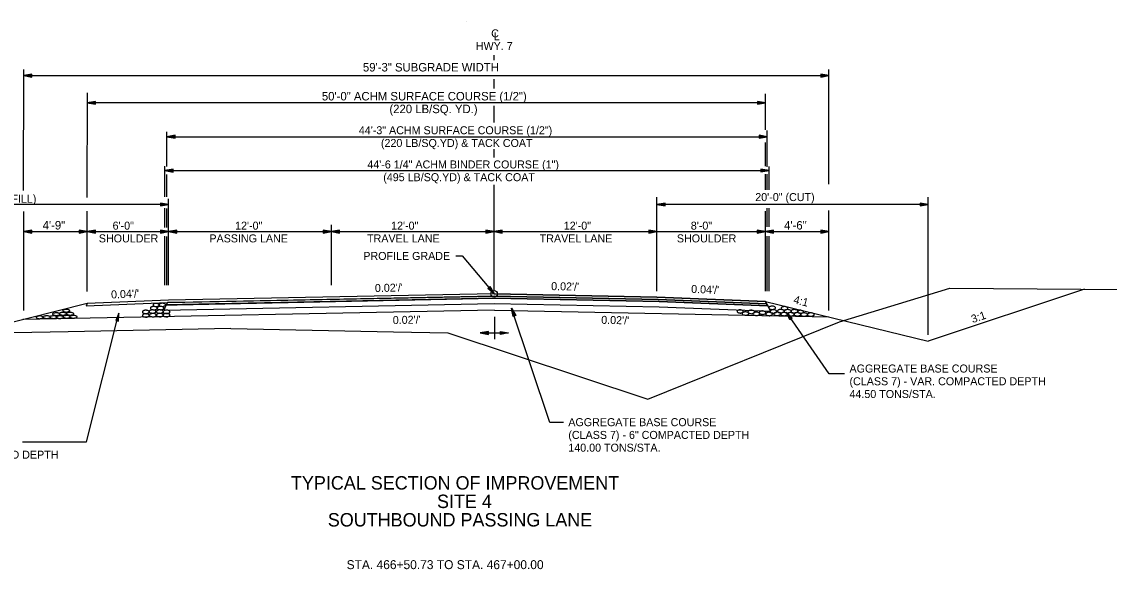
# Model space of a CAD drawing. Extents: x 1398183 to 1398373, y 1967240 to 1968889.
# Drawn here: x 1398225.6 to 1398305.8, y 1967766.3 to 1967806.6 of the extents above; entities that cross this region are included whole.
import ezdxf

# ---------------------------------------------------------------- set-up
doc = ezdxf.new("R2010")
doc.units = 0
for name, color, linetype in [('1', 7, 'Continuous'), ('10', 7, 'Continuous'), ('19', 7, 'Continuous'), ('42', 7, 'Continuous'), ('7', 7, 'Continuous'), ('Level 1', 7, 'Continuous'), ('Level 9', 7, 'Continuous')]:
    doc.layers.add(name, color=color, linetype=linetype)

# ---------------------------------------------------------------- blocks, each defined once
blk = doc.blocks.new('ROCKS')
at = {"layer": '1'}
blk.add_spline([(0.013, 0.06), (0.053, 0.053), (0.107, 0.033), (0.133, 0.013), (0.133, -0.007), (0.12, -0.033), (0.107, -0.04), (0.073, -0.053), (0.033, -0.067), (0.013, -0.067), (-0.02, -0.06), (-0.06, -0.053), (-0.087, -0.047), (-0.113, -0.02), (-0.113, -0.007), (-0.107, 0.02), (-0.087, 0.033), (-0.067, 0.047), (-0.033, 0.053), (-0.02, 0.06), (0.013, 0.06)], degree=3, dxfattribs=at)
blk = doc.blocks.new('4TO1 ABC')
at = {"layer": '1', "xscale": 0.1312491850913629, "yscale": 0.1312491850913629, "rotation": 180}
for p in [(0.00175, -0.00875), (-0.03325, -0.0385), (-0.016625, -0.023625), (0, -0.0385), (0.018375, -0.023625), (0.034125, -0.04025), (0.051625, -0.025375), (0.06475, -0.04025), (0.098, -0.04025), (0.133, -0.041125)]:
    blk.add_blockref('ROCKS', p, dxfattribs=at)

msp = doc.modelspace()

# ---------------------------------------------------------------- linework, layer by layer
at = {"layer": '1'}
msp.add_line((1398258.385, 1967806.631), (1398258.385, 1967806.631), dxfattribs=at)
msp.add_line((1398258.385, 1967806.631), (1398258.385, 1967806.631), dxfattribs=at)
at = {"layer": '19'}
for p, q in [((1398225.76, 1967794.194), (1398225.776, 1967803.114)), ((1398226.376, 1967802.762), (1398225.776, 1967802.657)), ((1398225.776, 1967802.657), (1398285.131, 1967802.657)), ((1398225.776, 1967802.657), (1398226.376, 1967802.552)), ((1398226.376, 1967802.707), (1398225.936, 1967802.672)), ((1398225.936, 1967802.642), (1398226.376, 1967802.602)), ((1398226.376, 1967802.552), (1398226.376, 1967802.762)), ((1398284.531, 1967802.762), (1398284.531, 1967802.552)), ((1398285.131, 1967802.657), (1398284.531, 1967802.762)), ((1398284.971, 1967802.672), (1398284.531, 1967802.707)), ((1398284.531, 1967802.552), (1398285.131, 1967802.657)), ((1398284.531, 1967802.602), (1398284.971, 1967802.642)), ((1398285.125, 1967794.648), (1398285.131, 1967803.114)), ((1398230.434, 1967793.677), (1398230.459, 1967801.394)), ((1398280.45, 1967798.665), (1398280.452, 1967801.304)), ((1398231.052, 1967800.762), (1398230.452, 1967800.657)), ((1398230.452, 1967800.657), (1398231.052, 1967800.552)), ((1398280.452, 1967800.657), (1398230.452, 1967800.657)), ((1398231.052, 1967800.707), (1398230.612, 1967800.672)), ((1398230.612, 1967800.642), (1398231.052, 1967800.602)), ((1398231.052, 1967800.552), (1398231.052, 1967800.762)), ((1398279.852, 1967800.762), (1398279.852, 1967800.552)), ((1398280.452, 1967800.657), (1398279.852, 1967800.762)), ((1398280.292, 1967800.672), (1398279.852, 1967800.707)), ((1398279.852, 1967800.552), (1398280.452, 1967800.657)), ((1398279.852, 1967800.602), (1398280.292, 1967800.642)), ((1398280.575, 1967795.932), (1398280.575, 1967798.613)), ((1398236.32, 1967795.966), (1398236.32, 1967798.516)), ((1398236.92, 1967798.262), (1398236.32, 1967798.157)), ((1398236.32, 1967798.157), (1398280.575, 1967798.157)), ((1398236.32, 1967798.157), (1398236.92, 1967798.052)), ((1398236.92, 1967798.207), (1398236.48, 1967798.172)), ((1398236.48, 1967798.142), (1398236.92, 1967798.102)), ((1398236.92, 1967798.052), (1398236.92, 1967798.262)), ((1398279.975, 1967798.263), (1398279.975, 1967798.053)), ((1398280.575, 1967798.158), (1398279.975, 1967798.263)), ((1398280.415, 1967798.173), (1398279.975, 1967798.208)), ((1398279.975, 1967798.053), (1398280.575, 1967798.158)), ((1398279.975, 1967798.103), (1398280.415, 1967798.143)), ((1398280.447, 1967795.971), (1398280.449, 1967797.722)), ((1398236.181, 1967793.713), (1398236.181, 1967795.982)), ((1398236.781, 1967795.762), (1398236.181, 1967795.657)), ((1398236.181, 1967795.657), (1398280.711, 1967795.657)), ((1398236.181, 1967795.657), (1398236.781, 1967795.552)), ((1398236.781, 1967795.707), (1398236.341, 1967795.672)), ((1398236.341, 1967795.642), (1398236.781, 1967795.602)), ((1398236.781, 1967795.552), (1398236.781, 1967795.762)), ((1398280.111, 1967795.763), (1398280.111, 1967795.553)), ((1398280.711, 1967795.658), (1398280.111, 1967795.763)), ((1398280.551, 1967795.673), (1398280.111, 1967795.708)), ((1398280.111, 1967795.553), (1398280.711, 1967795.658)), ((1398280.111, 1967795.603), (1398280.551, 1967795.643)), ((1398280.711, 1967794.242), (1398280.711, 1967795.962)), ((1398236.32, 1967793.714), (1398236.32, 1967795.359)), ((1398280.445, 1967794.242), (1398280.446, 1967795.387)), ((1398280.575, 1967794.242), (1398280.575, 1967795.387)), ((1398236.447, 1967793.157), (1398212.447, 1967793.157)), ((1398235.847, 1967793.262), (1398235.847, 1967793.052)), ((1398236.447, 1967793.157), (1398235.847, 1967793.262)), ((1398236.287, 1967793.172), (1398235.847, 1967793.207)), ((1398235.847, 1967793.052), (1398236.447, 1967793.157)), ((1398235.847, 1967793.102), (1398236.287, 1967793.142)), ((1398272.447, 1967786.756), (1398272.447, 1967793.703)), ((1398273.047, 1967793.262), (1398272.447, 1967793.157)), ((1398292.447, 1967793.157), (1398272.447, 1967793.157)), ((1398272.447, 1967793.157), (1398273.047, 1967793.052)), ((1398273.047, 1967793.207), (1398272.607, 1967793.172)), ((1398272.607, 1967793.142), (1398273.047, 1967793.102)), ((1398273.047, 1967793.052), (1398273.047, 1967793.262)), ((1398291.847, 1967793.262), (1398291.847, 1967793.052)), ((1398292.447, 1967793.157), (1398291.847, 1967793.262)), ((1398292.287, 1967793.172), (1398291.847, 1967793.207)), ((1398291.847, 1967793.052), (1398292.447, 1967793.157)), ((1398291.847, 1967793.102), (1398292.287, 1967793.142)), ((1398225.769, 1967785.335), (1398225.769, 1967792.646)), ((1398230.447, 1967786.754), (1398230.447, 1967792.672)), ((1398236.182, 1967791.464), (1398236.182, 1967792.88)), ((1398236.32, 1967791.467), (1398236.32, 1967792.874)), ((1398280.447, 1967786.757), (1398280.447, 1967792.655)), ((1398280.575, 1967791.516), (1398280.575, 1967792.885)), ((1398280.711, 1967791.514), (1398280.711, 1967792.881)), ((1398285.125, 1967785.35), (1398285.124, 1967792.711)), ((1398248.447, 1967787.2), (1398248.447, 1967791.661)), ((1398226.369, 1967791.262), (1398225.769, 1967791.157)), ((1398225.769, 1967791.157), (1398230.447, 1967791.157)), ((1398225.769, 1967791.157), (1398226.369, 1967791.052)), ((1398226.369, 1967791.207), (1398225.929, 1967791.172)), ((1398225.929, 1967791.142), (1398226.369, 1967791.102)), ((1398226.369, 1967791.052), (1398226.369, 1967791.262)), ((1398229.847, 1967791.262), (1398229.847, 1967791.052)), ((1398230.447, 1967791.157), (1398229.847, 1967791.262)), ((1398230.287, 1967791.172), (1398229.847, 1967791.207)), ((1398229.847, 1967791.052), (1398230.447, 1967791.157)), ((1398229.847, 1967791.102), (1398230.287, 1967791.142)), ((1398231.047, 1967791.262), (1398230.447, 1967791.157)), ((1398230.447, 1967791.157), (1398246.447, 1967791.157)), ((1398230.447, 1967791.157), (1398231.047, 1967791.052)), ((1398231.047, 1967791.207), (1398230.607, 1967791.172)), ((1398230.607, 1967791.142), (1398231.047, 1967791.102)), ((1398231.047, 1967791.052), (1398231.047, 1967791.262)), ((1398235.847, 1967791.262), (1398235.847, 1967791.052)), ((1398236.447, 1967791.157), (1398235.847, 1967791.262)), ((1398236.287, 1967791.172), (1398235.847, 1967791.207)), ((1398235.847, 1967791.052), (1398236.447, 1967791.157)), ((1398235.847, 1967791.102), (1398236.287, 1967791.142)), ((1398236.182, 1967787.199), (1398236.182, 1967790.812)), ((1398236.32, 1967787.199), (1398236.32, 1967790.809)), ((1398237.047, 1967791.262), (1398236.447, 1967791.157)), ((1398236.447, 1967791.157), (1398237.047, 1967791.052)), ((1398237.047, 1967791.207), (1398236.607, 1967791.172)), ((1398236.607, 1967791.142), (1398237.047, 1967791.102)), ((1398237.047, 1967791.052), (1398237.047, 1967791.262)), ((1398246.447, 1967791.157), (1398258.447, 1967791.157)), ((1398247.847, 1967791.262), (1398247.847, 1967791.052)), ((1398248.447, 1967791.157), (1398247.847, 1967791.262)), ((1398248.287, 1967791.172), (1398247.847, 1967791.207)), ((1398247.847, 1967791.052), (1398248.447, 1967791.157)), ((1398247.847, 1967791.102), (1398248.287, 1967791.142)), ((1398249.047, 1967791.262), (1398248.447, 1967791.157)), ((1398248.447, 1967791.157), (1398249.047, 1967791.052)), ((1398249.047, 1967791.207), (1398248.607, 1967791.172)), ((1398248.607, 1967791.142), (1398249.047, 1967791.102)), ((1398249.047, 1967791.052), (1398249.047, 1967791.262)), ((1398258.447, 1967791.157), (1398280.447, 1967791.157)), ((1398259.847, 1967791.262), (1398259.847, 1967791.052)), ((1398260.447, 1967791.157), (1398259.847, 1967791.262)), ((1398260.287, 1967791.172), (1398259.847, 1967791.207)), ((1398259.847, 1967791.052), (1398260.447, 1967791.157)), ((1398259.847, 1967791.102), (1398260.287, 1967791.142)), ((1398261.047, 1967791.262), (1398260.447, 1967791.157)), ((1398260.447, 1967791.157), (1398261.047, 1967791.052)), ((1398261.047, 1967791.207), (1398260.607, 1967791.172)), ((1398260.607, 1967791.142), (1398261.047, 1967791.102)), ((1398261.047, 1967791.052), (1398261.047, 1967791.262)), ((1398271.847, 1967791.262), (1398271.847, 1967791.052)), ((1398272.447, 1967791.157), (1398271.847, 1967791.262)), ((1398272.287, 1967791.172), (1398271.847, 1967791.207)), ((1398271.847, 1967791.052), (1398272.447, 1967791.157)), ((1398271.847, 1967791.102), (1398272.287, 1967791.142)), ((1398279.847, 1967791.262), (1398279.847, 1967791.052)), ((1398280.447, 1967791.157), (1398279.847, 1967791.262)), ((1398280.287, 1967791.172), (1398279.847, 1967791.207)), ((1398279.847, 1967791.052), (1398280.447, 1967791.157)), ((1398279.847, 1967791.102), (1398280.287, 1967791.142)), ((1398281.047, 1967791.262), (1398280.447, 1967791.158)), ((1398281.047, 1967791.262), (1398280.447, 1967791.157)), ((1398280.447, 1967791.158), (1398281.047, 1967791.052)), ((1398280.447, 1967791.157), (1398285.124, 1967791.157)), ((1398280.447, 1967791.157), (1398281.047, 1967791.052)), ((1398280.576, 1967786.757), (1398280.576, 1967790.819)), ((1398281.047, 1967791.207), (1398280.607, 1967791.173)), ((1398281.047, 1967791.207), (1398280.607, 1967791.172)), ((1398280.607, 1967791.143), (1398281.047, 1967791.102)), ((1398280.607, 1967791.142), (1398281.047, 1967791.102)), ((1398280.711, 1967786.757), (1398280.711, 1967790.821)), ((1398281.047, 1967791.052), (1398281.047, 1967791.262)), ((1398281.047, 1967791.052), (1398281.047, 1967791.262)), ((1398284.524, 1967791.262), (1398284.524, 1967791.052)), ((1398285.124, 1967791.157), (1398284.524, 1967791.262)), ((1398284.964, 1967791.172), (1398284.524, 1967791.207)), ((1398284.524, 1967791.052), (1398285.124, 1967791.157)), ((1398284.524, 1967791.102), (1398284.964, 1967791.142)), ((1398259.981, 1967786.965), (1398260.141, 1967787.099)), ((1398260.447, 1967786.573), (1398259.981, 1967786.965)), ((1398260.337, 1967786.688), (1398260.025, 1967786.996)), ((1398260.108, 1967787.067), (1398260.355, 1967786.706)), ((1398260.141, 1967787.099), (1398260.447, 1967786.573)), ((1398303.957, 1967786.909), (1398292.448, 1967783.072)), ((1398230.447, 1967785.854), (1398212.447, 1967781.354)), ((1398230.447, 1967785.854), (1398230.362, 1967785.684)), ((1398236.447, 1967786.094), (1398230.447, 1967785.854)), ((1398236.362, 1967785.924), (1398236.277, 1967785.754)), ((1398260.447, 1967786.574), (1398236.447, 1967786.094)), ((1398260.447, 1967786.574), (1398272.447, 1967786.334)), ((1398271.924, 1967786.004), (1398260.447, 1967786.24)), ((1398272.447, 1967786.334), (1398280.447, 1967786.014)), ((1398280.447, 1967786.014), (1398292.448, 1967783.072)), ((1398280.447, 1967786.014), (1398280.532, 1967785.844)), ((1398280.532, 1967785.844), (1398280.617, 1967785.674)), ((1398260.47, 1967785.362), (1398225.697, 1967784.666)), ((1398230.397, 1967775.667), (1398232.788, 1967785.143)), ((1398232.79, 1967785.151), (1398232.546, 1967784.593)), ((1398232.741, 1967785), (1398232.599, 1967784.584)), ((1398232.701, 1967784.557), (1398232.768, 1967784.993)), ((1398232.749, 1967784.545), (1398232.79, 1967785.151)), ((1398236.277, 1967785.754), (1398236.088, 1967785.375)), ((1398260.47, 1967785.362), (1398285.119, 1967784.869)), ((1398264.544, 1967777.089), (1398261.739, 1967785.509)), ((1398261.841, 1967784.91), (1398261.739, 1967785.509)), ((1398261.739, 1967785.509), (1398262.038, 1967784.978)), ((1398261.887, 1967784.927), (1398261.777, 1967785.354)), ((1398261.804, 1967785.364), (1398261.987, 1967784.964)), ((1398262.038, 1967784.978), (1398261.841, 1967784.91)), ((1398272.612, 1967785.619), (1398280.809, 1967785.291)), ((1398280.617, 1967785.674), (1398280.809, 1967785.291)), ((1398280.809, 1967785.291), (1398280.617, 1967785.674)), ((1398285.136, 1967780.661), (1398281.991, 1967785.213)), ((1398282.244, 1967784.661), (1398281.991, 1967785.213)), ((1398281.991, 1967785.213), (1398282.416, 1967784.778)), ((1398282.284, 1967784.689), (1398282.067, 1967785.073)), ((1398282.091, 1967785.089), (1398282.371, 1967784.75)), ((1398232.546, 1967784.593), (1398232.749, 1967784.545)), ((1398282.416, 1967784.778), (1398282.244, 1967784.661)), ((1398286.287, 1967780.661), (1398285.136, 1967780.661)), ((1398265.557, 1967777.089), (1398264.544, 1967777.089)), ((1398225.669, 1967775.667), (1398230.397, 1967775.667))]:
    msp.add_line(p, q, dxfattribs=at)
for points in [[(1398257.611, 1967789.36), (1398258.101, 1967789.36), (1398260.447, 1967786.573)], [(1398257.039, 1967783.694), (1398271.783, 1967778.793), (1398285.898, 1967784.503), (1398294.031, 1967786.983), (1398323.027, 1967786.767)], [(1398230.362, 1967785.684), (1398236.362, 1967785.924), (1398260.447, 1967786.406), (1398272.532, 1967786.164), (1398280.532, 1967785.844)], [(1398260.447, 1967786.24), (1398236.277, 1967785.754), (1398236.088, 1967785.375)], [(1398236.088, 1967785.375), (1398260.447, 1967785.865), (1398272.612, 1967785.619)], [(1398236.088, 1967785.375), (1398260.447, 1967785.865), (1398272.612, 1967785.619)], [(1398272.616, 1967785.994), (1398260.447, 1967786.24), (1398236.277, 1967785.754)], [(1398280.617, 1967785.674), (1398272.616, 1967785.994), (1398271.924, 1967786.004)], [(1398272.616, 1967785.994), (1398280.617, 1967785.674)], [(1398272.612, 1967785.619), (1398280.809, 1967785.291)], [(1398229.04, 1967783.774), (1398225.041, 1967783.694)], [(1398241.04, 1967784.014), (1398229.04, 1967783.774)], [(1398241.04, 1967784.014), (1398253.04, 1967783.774)], [(1398253.04, 1967783.774), (1398257.039, 1967783.694)]]:
    msp.add_lwpolyline(points, dxfattribs=at)
for points in [[(1398230.362, 1967785.684), (1398236.362, 1967785.924), (1398260.447, 1967786.406), (1398272.532, 1967786.164), (1398280.532, 1967785.844), (1398280.447, 1967786.014), (1398272.447, 1967786.334), (1398260.447, 1967786.574), (1398236.447, 1967786.094), (1398230.447, 1967785.854)], [(1398236.362, 1967785.924), (1398236.277, 1967785.754), (1398237.078, 1967785.77), (1398260.447, 1967786.24), (1398272.616, 1967785.994), (1398280.617, 1967785.674), (1398280.532, 1967785.844), (1398272.532, 1967786.164), (1398260.447, 1967786.406), (1398237.02, 1967785.937)]]:
    msp.add_lwpolyline(points, close=True, dxfattribs=at)
at = {"layer": '42'}
for p, q in [((1398260.47, 1967784.864), (1398260.47, 1967783.232)), ((1398260.023, 1967783.788), (1398259.423, 1967783.683)), ((1398259.423, 1967783.683), (1398260.023, 1967783.578)), ((1398259.423, 1967783.683), (1398261.518, 1967783.683)), ((1398260.023, 1967783.733), (1398259.583, 1967783.698)), ((1398259.583, 1967783.668), (1398260.023, 1967783.628)), ((1398260.023, 1967783.578), (1398260.023, 1967783.788)), ((1398260.918, 1967783.578), (1398260.918, 1967783.788)), ((1398260.918, 1967783.788), (1398261.518, 1967783.683)), ((1398260.918, 1967783.733), (1398261.358, 1967783.698)), ((1398261.518, 1967783.683), (1398260.918, 1967783.578)), ((1398261.358, 1967783.668), (1398260.918, 1967783.628))]:
    msp.add_line(p, q, dxfattribs=at)
at = {"layer": '7'}
for p, q in [((1398260.461, 1967803.806), (1398260.454, 1967804.157)), ((1398260.454, 1967801.721), (1398260.454, 1967802.399)), ((1398260.45, 1967799.199), (1398260.454, 1967800.421)), ((1398260.448, 1967796.617), (1398260.448, 1967797.247)), ((1398260.447, 1967786.756), (1398260.447, 1967794.603)), ((1398236.447, 1967787.199), (1398236.447, 1967793.581)), ((1398292.448, 1967783.553), (1398292.447, 1967793.704))]:
    msp.add_line(p, q, dxfattribs=at)
at = {"layer": 'Level 9'}
msp.add_circle((1398260.447, 1967786.573), 0.25, dxfattribs=at)

# ---------------------------------------------------------------- block references
at = {"layer": '19', "xscale": 14.999970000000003, "yscale": -14.999970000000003, "rotation": -180}
msp.add_blockref('4TO1 ABC', (1398228.917, 1967785.451), dxfattribs=at)
at = {"layer": 'Level 1'}
for p, xscale, yscale, rotation in [((1398235.511, 1967785.753), 1.877174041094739, 1.8771740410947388, -0.17361855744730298), ((1398235.971, 1967785.765), 1.849824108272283, 1.8498241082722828, -0.17361855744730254), ((1398234.747, 1967785.242), 2.011654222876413, 2.0116542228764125, -0.17361855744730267), ((1398234.753, 1967784.984), 2.011654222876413, 2.0116542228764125, -0.17361855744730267), ((1398235.244, 1967785.271), 2.011654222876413, 2.0116542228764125, -0.17361855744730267), ((1398235.276, 1967785.005), 2.011654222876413, 2.0116542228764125, -0.17361855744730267), ((1398235.337, 1967785.521), 2.011654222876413, 2.0116542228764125, -0.17361855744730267), ((1398235.78, 1967785.269), 2.011654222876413, 2.0116542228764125, -0.17361855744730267), ((1398235.788, 1967785.009), 2.011654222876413, 2.0116542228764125, -0.17361855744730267), ((1398235.834, 1967785.528), 2.011654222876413, 2.0116542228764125, -0.17361855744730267), ((1398236.281, 1967785.248), 2.011654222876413, 2.0116542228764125, -0.17361855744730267), ((1398236.281, 1967785.006), 2.011654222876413, 2.0116542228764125, -0.17361855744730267), ((1398278.571, 1967785.276), 1.8429465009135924, 1.8429465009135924, -0.17361855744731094), ((1398278.957, 1967785.124), 2.011654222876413, 2.0116542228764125, -0.17361855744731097), ((1398279.387, 1967785.241), 2.011654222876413, 2.0116542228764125, -0.17361855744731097), ((1398279.757, 1967785.1), 2.011654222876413, 2.0116542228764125, -0.17361855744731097), ((1398280.213, 1967785.189), 2.011654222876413, 2.0116542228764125, -0.17361855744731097), ((1398280.696, 1967785.09), 2.011654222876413, 2.0116542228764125, -0.17361855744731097), ((1398280.925, 1967785.546), 2.011654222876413, 2.0116542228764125, -0.17361855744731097), ((1398281.017, 1967785.279), 2.011654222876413, 2.0116542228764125, -0.17361855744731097), ((1398281.297, 1967785.096), 2.011654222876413, 2.0116542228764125, -0.17361855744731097), ((1398281.297, 1967785.096), 2.011654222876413, 2.0116542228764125, -0.17361855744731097), ((1398281.567, 1967785.303), 2.011654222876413, 2.0116542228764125, -0.17361855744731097), ((1398281.801, 1967785.085), 2.011654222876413, 2.0116542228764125, -0.17361855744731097), ((1398281.801, 1967785.085), 2.011654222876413, 2.0116542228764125, -0.17361855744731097), ((1398281.836, 1967785.51), 2.011654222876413, 2.0116542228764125, -0.17361855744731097), ((1398282.067, 1967785.29), 2.011654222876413, 2.0116542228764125, -0.17361855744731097), ((1398282.293, 1967785.067), 2.011654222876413, 2.0116542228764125, -0.17361855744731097), ((1398282.293, 1967785.067), 2.011654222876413, 2.0116542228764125, -0.17361855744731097), ((1398282.563, 1967785.29), 2.011654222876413, 2.0116542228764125, -0.17361855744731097), ((1398282.783, 1967785.067), 2.011654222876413, 2.0116542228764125, -0.17361855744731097), ((1398282.783, 1967785.067), 2.011654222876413, 2.0116542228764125, -0.17361855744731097), ((1398283.024, 1967785.251), 1.7335100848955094, 1.7335100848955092, -0.173618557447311), ((1398283.276, 1967785.047), 2.011654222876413, 2.0116542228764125, -0.17361855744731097), ((1398283.276, 1967785.047), 2.011654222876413, 2.0116542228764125, -0.17361855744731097), ((1398283.779, 1967785.047), 2.011654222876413, 2.0116542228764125, -0.17361855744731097), ((1398283.779, 1967785.047), 2.011654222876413, 2.0116542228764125, -0.17361855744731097)]:
    msp.add_blockref('ROCKS', p, dxfattribs=dict(at, xscale=xscale, yscale=yscale, rotation=rotation))

# ---------------------------------------------------------------- texts
at = {"layer": '10'}
for s, height, rotation, p in [('24\'-0" (FILL)', 0.59001, 0, (1398222.369, 1967793.286)), ('20\'-0" (CUT)', 0.59001, 0, (1398279.697, 1967793.409)), ('6\'-0" ', 0.59, 0, (1398232.319, 1967791.302)), ('12\'-0"', 0.59, 0, (1398241.35, 1967791.302)), ('12\'-0"', 0.59, 0, (1398252.851, 1967791.302)), ('12\'-0"', 0.59, 0, (1398265.58, 1967791.302)), ('8\'-0" ', 0.59, 0, (1398274.946, 1967791.302)), ('SHOULDER', 0.59, 0, (1398231.306, 1967790.362)), ('PASSING LANE', 0.59001, 0, (1398239.457, 1967790.362)), ('TRAVEL LANE', 0.59001, 0, (1398251.079, 1967790.362)), ('TRAVEL LANE', 0.59001, 0, (1398263.808, 1967790.362)), ('SHOULDER', 0.59, 0, (1398273.919, 1967790.362)), ('PROFILE GRADE', 0.59001, 0.00316, (1398250.803, 1967789.068)), ('4:1', 0.59, 346.26361, (1398282.471, 1967785.881)), ('3:1', 0.59, 18.47764, (1398295.725, 1967784.41))]:
    msp.add_text(s, height=height, rotation=rotation, dxfattribs=at).set_placement(p)
at = {"layer": '19'}
for s, height, p in [('C', 0.59, (1398260.229, 1967805.48)), ('L', 0.59, (1398260.418, 1967805.269)), ('HWY. 7', 0.59, (1398259.098, 1967804.55)), ('59\'-3" SUBGRADE WIDTH', 0.625, (1398250.774, 1967802.964)), ('50\'-0" ACHM SURFACE COURSE (1/2")', 0.625, (1398247.746, 1967800.829)), ('(220 LB/SQ. YD.)', 0.625, (1398252.726, 1967799.891)), ('4\'-9"', 0.625, (1398227.161, 1967791.315)), ('4\'-6"', 0.625, (1398281.824, 1967791.31)), ('TYPICAL SECTION OF IMPROVEMENT', 0.98999, (1398245.467, 1967772.138)), ('SITE 4', 0.99, (1398256.236, 1967770.777)), ('SOUTHBOUND PASSING LANE', 0.98999, (1398248.184, 1967769.416)), ('STA. 466+50.73 TO STA. 467+00.00', 0.65999, (1398249.572, 1967766.273))]:
    msp.add_text(s, height=height, dxfattribs=at).set_placement(p)
for s, height, rotation, p in [("0.02'/'", 0.59, 358.85424, (1398264.646, 1967786.846)), ("0.04'/'", 0.59, 2.29061, (1398232.216, 1967786.226)), ("0.02'/'", 0.59, 1.14576, (1398251.662, 1967786.702)), ("0.04'/'", 0.59, 357.70939, (1398274.962, 1967786.642)), ("0.02'/'", 0.59, 1.14576, (1398252.98, 1967784.338)), ("0.02'/'", 0.59, 358.85424, (1398268.338, 1967784.36)), ('AGGREGATE BASE COURSE', 0.59001, 360, (1398286.644, 1967780.768)), ('(CLASS 7) - VAR. COMPACTED DEPTH', 0.59001, 360, (1398286.644, 1967779.828)), ('44.50 TONS/STA.', 0.59001, 360, (1398286.644, 1967778.888)), ('AGGREGATE BASE COURSE', 0.59001, 360, (1398265.916, 1967776.813)), ('(CLASS 7) - 6" COMPACTED DEPTH', 0.59001, 360, (1398265.916, 1967775.873)), ('140.00 TONS/STA.', 0.59001, 360, (1398265.916, 1967774.933)), ('(CLASS 7) - VAR. COMPACTED DEPTH', 0.59001, 360, (1398213.863, 1967774.415))]:
    msp.add_text(s, height=height, rotation=rotation, dxfattribs=at).set_placement(p)
at = {"layer": '42'}
for s, p in [('44\'-3" ACHM SURFACE COURSE (1/2")', (1398250.472, 1967798.336)), ('(220 LB/SQ.YD) & TACK COAT', (1398252.1, 1967797.396)), ('44\'-6 1/4" ACHM BINDER COURSE (1")', (1398251.099, 1967795.815)), ('(495 LB/SQ.YD) & TACK COAT', (1398252.272, 1967794.875))]:
    msp.add_text(s, height=0.59001, rotation=360, dxfattribs=at).set_placement(p)

doc.saveas('drawing.dxf')
